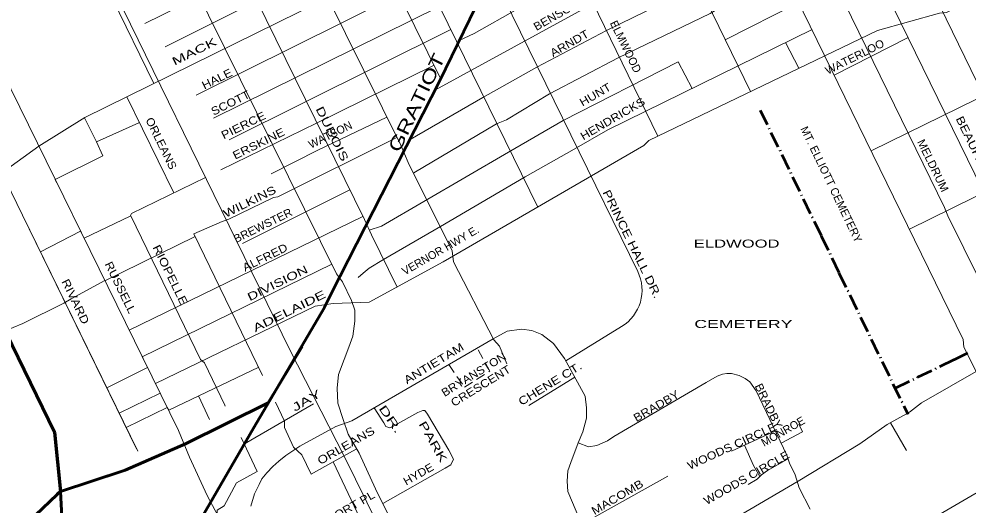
# Model space of a CAD drawing. Extents: x 34705 to 138605, y 34275 to 143551.
# Drawn here: x 100351 to 109243, y 104335 to 108885 of the extents above; entities that cross this region are included whole.
import ezdxf
from ezdxf.enums import TextEntityAlignment as Align

# ---------------------------------------------------------------- set-up
doc = ezdxf.new("R2010")
doc.units = 0
doc.header["$LTSCALE"] = 30
doc.linetypes.add('DOT_DASHED', pattern=[7.7, 5, -1.2, 0.3, -1.2])
doc.linetypes.add('MEDIUM_DASHED', pattern=[4.5, 3, -1.5])
for name, color, linetype, lineweight in [('1', 7, 'Continuous', 13), ('11', 7, 'Continuous', 13), ('50', 7, 'Continuous', 13), ('51', 7, 'Continuous', 35)]:
    doc.layers.add(name, color=color, linetype=linetype, lineweight=lineweight)

msp = doc.modelspace()

# ---------------------------------------------------------------- linework, layer by layer
at = {"layer": '1'}
for p, q in [((102907.45, 113137.64), (106147.78, 106522.3)), ((101531.27, 108841.79), (103003.94, 109570.01)), ((102010.55, 108172.35), (104435.15, 109376.27)), ((101179.4, 109171.09), (101613.2, 108281.84)), ((106967.75, 108690.6), (107657.67, 109038.06)), ((102173.49, 107956.97), (104290.98, 109001.05)), ((107532.61, 108663.53), (107658.47, 108423.71)), ((107989.09, 108359.61), (108680.46, 108711.36)), ((106525.92, 108484.26), (106657.26, 108234)), ((101360.93, 108156.02), (101802.29, 107257.06)), ((101077.51, 107735.19), (101475.18, 107913.31)), ((102447, 106784), (103452.37, 107283.85)), ((101384.92, 105970.73), (103573.94, 107036.48)), ((101990.32, 106872.12), (102633.98, 105547.42)), ((105474.27, 105684.25), (105997.73, 106005.4)), ((105128.24, 105266.13), (105558.37, 105530.02)), ((102033.52, 105355.94), (102135.51, 105135.07)), ((108515.85, 105103.72), (108667.11, 104843.48)), ((107025.33, 104838.33), (107437.6, 105028.26)), ((102431.7, 104965.83), (102581.71, 104649.65)), ((103293.83, 104739.32), (103510.05, 104857.64)), ((105629.92, 104157.12), (106429.02, 104605.8))]:
    msp.add_line(p, q, dxfattribs=at)
at = {"layer": '1', "linetype": 'MEDIUM_DASHED'}
msp.add_line((104763.14, 105589.29), (104644.61, 105804.53), dxfattribs=at)
at = {"layer": '1', "lineweight": 53}
msp.add_lwpolyline([(101368.9, 103017.54), (102548.84, 105055.11), (103212.24, 106184.42), (103282.07, 106324.13), (104294.63, 108304.78), (105138.43, 110039.49), (106145.17, 112117.65), (109289.05, 118526.78), (110743.87, 121478.11), (113275.26, 126686.61), (116465.7, 133274.74), (120395.18, 141348.71), (121157.51, 142914.61), (121243.66, 143093.14)], dxfattribs=at)
at = {"layer": '1'}
for points in [[(104051.67, 107444.7), (104825.64, 107904.58), (104918.75, 107939.5), (105320.28, 108183.99), (105966.22, 108521.62), (106827.48, 108934.92), (106920.59, 108993.14), (111031.93, 111010.18), (111770.98, 111376.91), (112521.67, 111784.39), (113970.67, 112564.43), (114040.5, 112512.04), (115093.8, 113076.69), (115128.71, 113117.44), (116414.78, 113815.98), (116887.6, 114070.66), (116969.07, 114143.43), (117091.27, 114347.17), (117143.65, 114399.56), (119333.43, 115468.66)], [(99622.96, 107156.95), (99848.68, 107262.79), (100188.92, 107440.65), (100537.2, 107693.33), (100968.9, 107962.79), (103779.62, 109348.23), (104572.5, 109741.16), (105072.96, 109985.65), (105247.54, 110090.43), (106097.16, 110492.09), (110265.23, 112549.88), (110957.73, 112899.15), (112028.48, 113475.45), (113105.05, 114057.56), (114210.72, 114761.93)], [(105838, 114523.9), (109374.69, 107291.74), (109999.77, 106037.98), (110044.65, 105954.61), (110041.44, 105944.98), (110594.62, 104809.15)], [(105410.48, 114313.93), (105596.68, 113932.88), (105674.36, 113970.97), (109022.08, 107118.58), (109054.14, 107041.62), (110256.75, 104612.72), (110148.21, 104549.61), (110451.51, 103928.7)], [(105127.85, 114217.1), (105159.44, 114152.16), (109198.39, 105884.06), (109204.8, 105813.52), (110220.52, 103795.66)], [(108341.95, 107654.27), (112091.04, 109493.76), (112638.05, 109773.17), (114482.77, 110762.77), (119517.92, 113453.62), (120145.08, 113798.95)], [(106799.91, 113452.41), (106840.73, 113369.76), (107129.23, 112773.34), (107417.73, 112183.33), (107469.02, 112106.37), (109733.71, 107458.48), (110333.15, 106230.37), (110944.91, 105012.82)], [(103353.47, 113354.48), (105016.75, 109958.19), (105072.96, 109985.65), (105223.97, 110076.29), (106336.04, 107787.44)], [(102383.21, 112882.78), (102570.99, 112500.78), (102615.86, 112417.41), (105211.22, 107124.24)], [(102123.39, 112756.47), (102314.54, 112366.11), (102353.01, 112276.32), (104302.15, 108320.24)], [(101569.9, 112487.39), (102370.64, 110849.41), (103928.52, 107702.17), (103999.04, 107541.84), (104409.35, 106714.55), (104422.17, 106611.94), (104800.42, 105880.85), (104851.71, 105823.13), (104922.23, 105656.39)], [(100612.15, 112021.77), (101795.25, 109613.28), (101827.31, 109529.91), (103325.88, 106499.72), (103383.58, 106422.76), (103466.93, 106249.61), (103498.98, 106159.82), (103498.98, 106057.21), (103479.75, 105916.12), (103441.28, 105813.51), (103396.41, 105698.08), (103345.12, 105556.99), (103332.3, 105428.73), (103338.71, 105287.64), (103389.99, 105133.72), (103434.87, 104999.05), (103537.45, 104819.48), (103691.31, 104486), (105116.13, 101623.89), (105586.11, 101897.14), (106074.33, 100898.57)], [(101237.33, 105303.94), (101290.09, 105195.91), (101674.44, 105382.43), (101630.74, 105471.24), (103126.41, 106197.51), (103295.16, 106220.8), (103632.68, 106232.44), (104325.18, 106610.82), (106206.27, 107700.84), (106252.83, 107747.41), (108394.33, 108777.75), (108976.26, 108940.75), (109040.27, 108946.57), (111770.98, 110288.35), (114407.12, 111691.25), (114494.41, 111766.93), (114535.14, 111830.96), (114597.08, 112016.83)], [(108694.04, 106916.51), (110914.08, 108009.36), (110983.91, 108137.42), (112635.16, 108945.15), (112682.5, 108869.82), (113035.66, 109049.25), (112992.31, 109135.14), (114826.11, 110110.8), (114855.2, 110151.55), (115729.79, 110618.71), (115812.95, 110462.89), (116350.76, 110762.77), (116705.74, 110960.69), (117271.04, 111258.63)], [(105699.4, 111197.48), (105789.32, 111118.77), (106443.25, 109772.01), (106609.94, 109425.7), (107204.08, 108205.08)], [(104252.68, 108222.73), (105727.63, 109028.06), (106588.89, 109441.37), (107277.02, 109796.46), (108400.15, 110349.47), (109556.71, 110904.33)], [(104476.48, 108684.61), (104616.14, 108748.65), (105023.5, 108981.49), (106838.09, 109878.74), (107160.54, 110055.73)], [(102204.57, 109822.95), (103588.74, 107006.36), (103652.85, 106865.27), (103894.54, 106375.52)], [(104015.09, 107757.98), (104697.61, 108149.07), (105203.89, 108434.3), (105855.65, 108777.75), (106734.37, 109208.52), (107405.05, 109534.51)], [(101719.59, 108624.95), (101719.59, 108624.95), (103122.87, 109329.75)], [(99858.25, 109072.97), (101846.54, 105032.72), (101949.12, 104782.61), (102115.8, 104423.47), (102367.74, 103949.45)], [(102318.98, 107753.23), (102318.98, 107753.23), (104396.26, 108786.33)], [(103527.94, 106465.29), (103574.49, 106506.04), (103632.68, 106552.6), (103766.53, 106634.1), (104301.9, 106942.62), (105093.33, 107408.32), (105553.05, 107665.91), (105867.29, 107846.37), (107781.07, 108785.45)], [(102325.17, 101481.39), (105929.85, 103550.33), (107652.36, 104557.4), (108228.47, 104906.67), (108485.98, 105087.12), (108695.48, 105203.55), (108806.04, 105290.86), (110963.55, 106527.87), (111516.38, 106842.21), (111597.85, 106900.42), (112267.07, 107238.05), (113064.31, 107633.89), (113442.57, 107808.52), (113768.45, 107965.7), (114776.41, 108513.55)], [(103631.77, 106907.98), (103749.07, 106944.08), (104936.21, 107636.8), (105448.3, 107933.68), (106525.92, 108484.26)], [(102241.16, 107471.64), (103139.5, 107910.4), (104233.52, 108448.85)], [(99364.51, 108152.23), (99750.13, 108345.09), (100384.82, 107049.64), (101453.37, 104861.55)], [(99364.51, 108152.23), (99750.13, 108345.09), (100384.82, 107049.64), (101442.45, 104883.91)], [(99364.51, 108152.23), (99750.13, 108345.09), (100384.82, 107049.64), (101464.42, 104838.92)], [(100964.79, 107960.76), (101077.21, 107735.85), (101136.93, 107604.42)], [(102713.24, 107435.97), (103149.68, 107657.17), (103798.84, 107964.15)], [(101157.12, 106433.64), (102000.85, 106849.78), (101990.32, 106872.12), (102253.51, 106987.74), (102317.52, 107011.02), (102736.51, 107214.76), (102777.25, 107220.59), (103892.3, 107775.34)], [(100703.62, 107355.16), (100689.8, 107383.24), (101136.93, 107604.42)], [(100553.26, 106705.7), (100928.68, 106897.83), (100961, 106832.16), (101393.71, 107040.13), (101405.35, 107063.41), (102097.55, 107401.5)], [(101398.07, 107042.22), (102051.69, 105696.47), (102088.55, 105666.01), (102280.88, 105270.01), (102284.33, 105261.14)], [(101127.94, 105527.95), (101175.49, 105430.58), (101556.02, 105623.07), (101506.61, 105723.46), (103280.97, 106590.52)], [(100207.62, 105958.03), (100386.97, 106033.07), (100771.04, 106225.17), (100840.88, 106265.91), (101155.71, 106436.5)], [(104794.84, 105891.65), (104923.83, 105962.63), (105058.46, 105981.87), (105154.63, 105969.04), (105250.79, 105930.56), (105359.78, 105847.19), (105462.36, 105706.1), (105654.69, 105353.38), (105667.51, 105244.36), (105667.51, 105148.16), (105635.46, 105019.9), (105590.58, 104917.29), (105520.06, 104731.31), (105494.41, 104654.35), (105488, 104558.15), (105494.41, 104461.96), (105571.35, 104275.97), (106468.89, 102454.65), (106539.41, 102377.69), (107033.07, 101345.18)], [(104794.84, 105891.65), (103468.52, 105122.51), (103321.07, 105071.2), (102981.29, 104885.22), (102851.47, 104797.04), (102787.36, 104745.74), (102729.66, 104694.43), (102671.96, 104636.71), (102627.08, 104578.99), (102601.44, 104527.69), (102556.56, 104437.91), (102524.5, 104322.47)], [(101356.4, 105060.12), (101740.26, 105248.68), (101753.84, 105221.08), (102598.3, 105625.58)], [(105590.58, 104917.29), (105686.75, 104878.81), (105763.68, 104891.63), (105866.26, 104936.53), (105923.95, 104975.01), (106789.45, 105481.64), (106892.02, 105539.36), (106943.31, 105558.6), (106981.78, 105565.01), (107026.65, 105565.01), (107097.18, 105545.77), (107154.87, 105520.12), (107199.75, 105488.06), (107257.45, 105404.68), (107545.95, 104801.85), (107571.59, 104724.89), (107622.88, 104615.87), (107661.35, 104494.02), (107763.92, 104295.21)], [(102462.96, 104906.81), (103050.75, 105248.66), (103109.44, 105282.22)], [(102754.84, 105296.98), (102840.25, 105119.29), (102840.25, 105061.57), (102923.59, 104875.59), (103000.53, 104805.05), (103088.68, 104623.89), (103293.83, 104739.32), (103633.61, 104027.47), (103665.67, 103963.33), (104306.77, 102699.95), (104345.24, 102590.93), (104479.87, 102327.99), (104563.22, 102167.66), (104742.23, 101782.97)], [(103679.71, 105244.97), (103768.25, 105103.26), (103787.48, 105071.2), (103825.95, 105058.37), (103870.82, 105077.61), (104088.8, 105199.46), (104133.68, 105218.7), (104152.91, 105218.7), (104178.55, 105186.63), (104377.3, 104846.74), (104422.17, 104763.37), (104396.53, 104712.06), (104345.24, 104680), (103759.56, 104348.01)], [(107491.91, 104914.77), (107692.39, 105020.32), (107657.02, 105091.09)], [(107148.89, 104895.25), (107231.81, 104705.65), (107292.91, 104601.75)], [(107181.99, 104526.18), (107267.9, 104576.73), (107308.33, 104617.17), (107363.92, 104657.61), (107552.53, 104765.42)], [(102810.77, 100633.3), (103044.93, 100795.46), (109763.19, 104704.2)], [(102002.01, 103819.39), (102208.88, 104178.81), (102208.88, 104287.73), (102274.21, 104325.85), (102388.54, 104543.68), (102581.71, 104649.65)]]:
    msp.add_lwpolyline(points, dxfattribs=at)
at = {"layer": '1', "linetype": 'DOT_DASHED', "lineweight": 53}
for points in [[(107295.95, 108030.85), (107866.67, 106855.46), (108033.36, 106509.15), (108678.55, 105183.64)], [(108560.53, 105428.74), (108769.84, 105530.38), (109116.15, 105697.07), (109241.21, 105757.94)]]:
    msp.add_lwpolyline(points, dxfattribs=at)
at = {"layer": '1', "linetype": 'MEDIUM_DASHED'}
msp.add_lwpolyline([(104378, 105649.93), (104524.67, 105436.67), (104760.97, 105587.9)], dxfattribs=at)
at = {"layer": '1'}
msp.add_arc((105788.56, 106346.35), 400, 301.52964, 26.09654, dxfattribs=at)
at = {"layer": '50'}
msp.add_lwpolyline([(104963.65, 101619.2), (103401.8, 104785.56), (102889.39, 105786.76), (100756.78, 110147.71), (99981.01, 111714.94)], dxfattribs=at)
at = {"layer": '51', "lineweight": 70}
msp.add_lwpolyline([(97910.12, 110708.17), (100683.69, 105015.92), (100740.7, 104462.71), (100708.3, 104431.99)], dxfattribs=at)
at = {"layer": '51', "lineweight": 60}
for points in [[(103003.68, 105819.57), (102687.36, 105290.92), (101910.91, 104906.13), (101346.47, 104660.89), (100740.7, 104462.71), (100764.62, 103988.25)], [(101317.21, 104650.97), (100741.76, 104462.71), (100765.99, 103982.21), (101152.14, 103319.84), (101362.05, 103122.99), (101624.44, 102860.51), (101847.47, 102584.91), (101945.87, 102427.43), (102878.59, 100484.41)], [(100708.3, 104431.99), (100301.7, 104046.37), (99460.75, 103701.33), (98388.89, 103068.27), (97510.88, 102543.58), (96878.03, 102018.88), (96266.56, 101672.41), (94157.06, 101062.17), (92788.73, 100605.91), (92053.25, 100332.16), (91322.06, 100332.16), (90426.94, 100400.6), (89697.17, 100337.86), (89332.28, 99932.93), (89286.67, 99488.08), (89309.48, 99071.74), (89383.59, 98792.29), (89913.82, 97593.19), (90193.19, 96937.32), (90347.13, 96349.89), (90369.93, 95910.74)]]:
    msp.add_lwpolyline(points, dxfattribs=at)

# ---------------------------------------------------------------- texts
at = {"layer": '11'}
for s, height, rotation, width, p in [('BENSON', 75, 29.774, 1.1, (105401.49, 108887.87)), ('ARNDT', 75, 29.692, 1.15, (105526.94, 108624.53)), ('MACK', 75, 26.288, 1.55, (102009.88, 108547.22)), ('WATERLOO', 75, 26.678, 1.05, (108197.74, 108497.04)), ('GRATIOT', 120, 64.174, 1.4, (104130.72, 108075.38)), ('HALE', 75, 26.284, 1.15, (102223.23, 108290.46)), ('SCOTT', 75, 26.285, 1.15, (102348.9, 108065.57)), ('HUNT', 75, 30.274, 1.15, (105769.39, 108144.42)), ('HENDRICKS', 75, 30.276, 1.15, (105931.9, 107918.36)), ('DUBOIS                                            ', 75, 296.282, 1.45, (103645.65, 106996.68)), ('ORLEANS', 75, 296.046, 1.1, (101650.68, 107703.81)), ('PIERCE', 75, 26.286, 1.2, (102469.87, 107855.67)), ('BEAUFAIT', 75, 296.059, 1.25, (109259.93, 107676.63)), ('ERSKINE', 75, 26.286, 1.2, (102613.22, 107684.74)), ('MELDRUM', 75, 296.059, 1.05, (108880.82, 107495.97)), ('WILKINS', 75, 26.286, 1.3, (102528.65, 107141.22)), ('PRINCE HALL DR.', 75, 296.097, 1.3, (106062.39, 106761.68)), ('BREWSTER', 75, 26.303, 1.05, (102652.94, 106918.33)), ('RIOPELLE', 75, 296.044, 1.25, (101735.37, 106472.27)), ('ALFRED', 75, 26.299, 1.15, (102672.84, 106619.11)), ('RUSSELL', 75, 296.043, 1.15, (101267.87, 106354.68)), ('DIVISION', 75, 26.304, 1.4, (102790.35, 106378.31)), ('RIVARD', 75, 295.848, 1.2, (100847.03, 106223.21)), ('ADELAIDE   ', 75, 26.304, 1.5, (102955.79, 106144.21)), ('ANTIETAM', 75, 31.305, 1.25, (104256.99, 105628.58)), ('BRYANSTON', 75, 31.53, 1.1, (104631.07, 105524.88)), ('CRESCENT', 75, 31.53, 1.15, (104696.44, 105418.34)), ('CHENE CT.', 75, 31.53, 1.25, (105346.52, 105438.6)), ('BRADBY', 75, 295.936, 1.1, (107341.77, 105245.96)), ('JAY   ', 75, 30.475, 1.6, (103120.46, 105314.97)), ('BRADBY', 75, 30.194, 1.15, (106340.9, 105229.02)), ('DR. ', 75, 304.532, 1.7, (103814.55, 105098)), ('PARK   ', 75, 299.639, 1.55, (104229.42, 104853.41)), ('WOODS CIRCLE', 75, 24.735, 1.15, (107045.44, 104851.93)), ('ORLEANS ', 75, 30.018, 1.25, (103449, 104867.15)), ('WOODS CIRCLE', 75, 29.812, 1.15, (107186.07, 104557.7)), ('HYDE', 75, 29.638, 1.1, (104112.03, 104591.35)), ('MACOMB ', 75, 30.337, 1.2, (105990.74, 104384.48)), ('CHATEAUFORT PL', 75, 30.019, 1.15, (103243.8, 104148.07))]:
    msp.add_text(s, height=height, rotation=rotation, dxfattribs=dict(at, width=width)).set_placement(p, align=Align.CENTER)
for s, rotation, p in [('ELMWOOD', 296.129, (106001.95, 108609.29)), ('WATSON', 26.288, (103284.17, 107767.61)), ('MT. ELLIOTT CEMETERY', 295.703, (107928.83, 107319.75)), (' VERNOR HWY E.', 30.091, (104305.81, 106680.06)), ('MONROE', 29.812, (107527.75, 104990.86))]:
    msp.add_text(s, height=75, rotation=rotation, dxfattribs=at).set_placement(p, align=Align.CENTER)
for s, width, p in [('ELDWOOD', 1.55, (107075.21, 106744.62)), ('CEMETERY', 1.65, (107138.03, 105991.69))]:
    msp.add_text(s, height=75, dxfattribs=dict(at, width=width)).set_placement(p, align=Align.CENTER)

doc.saveas('drawing.dxf')
